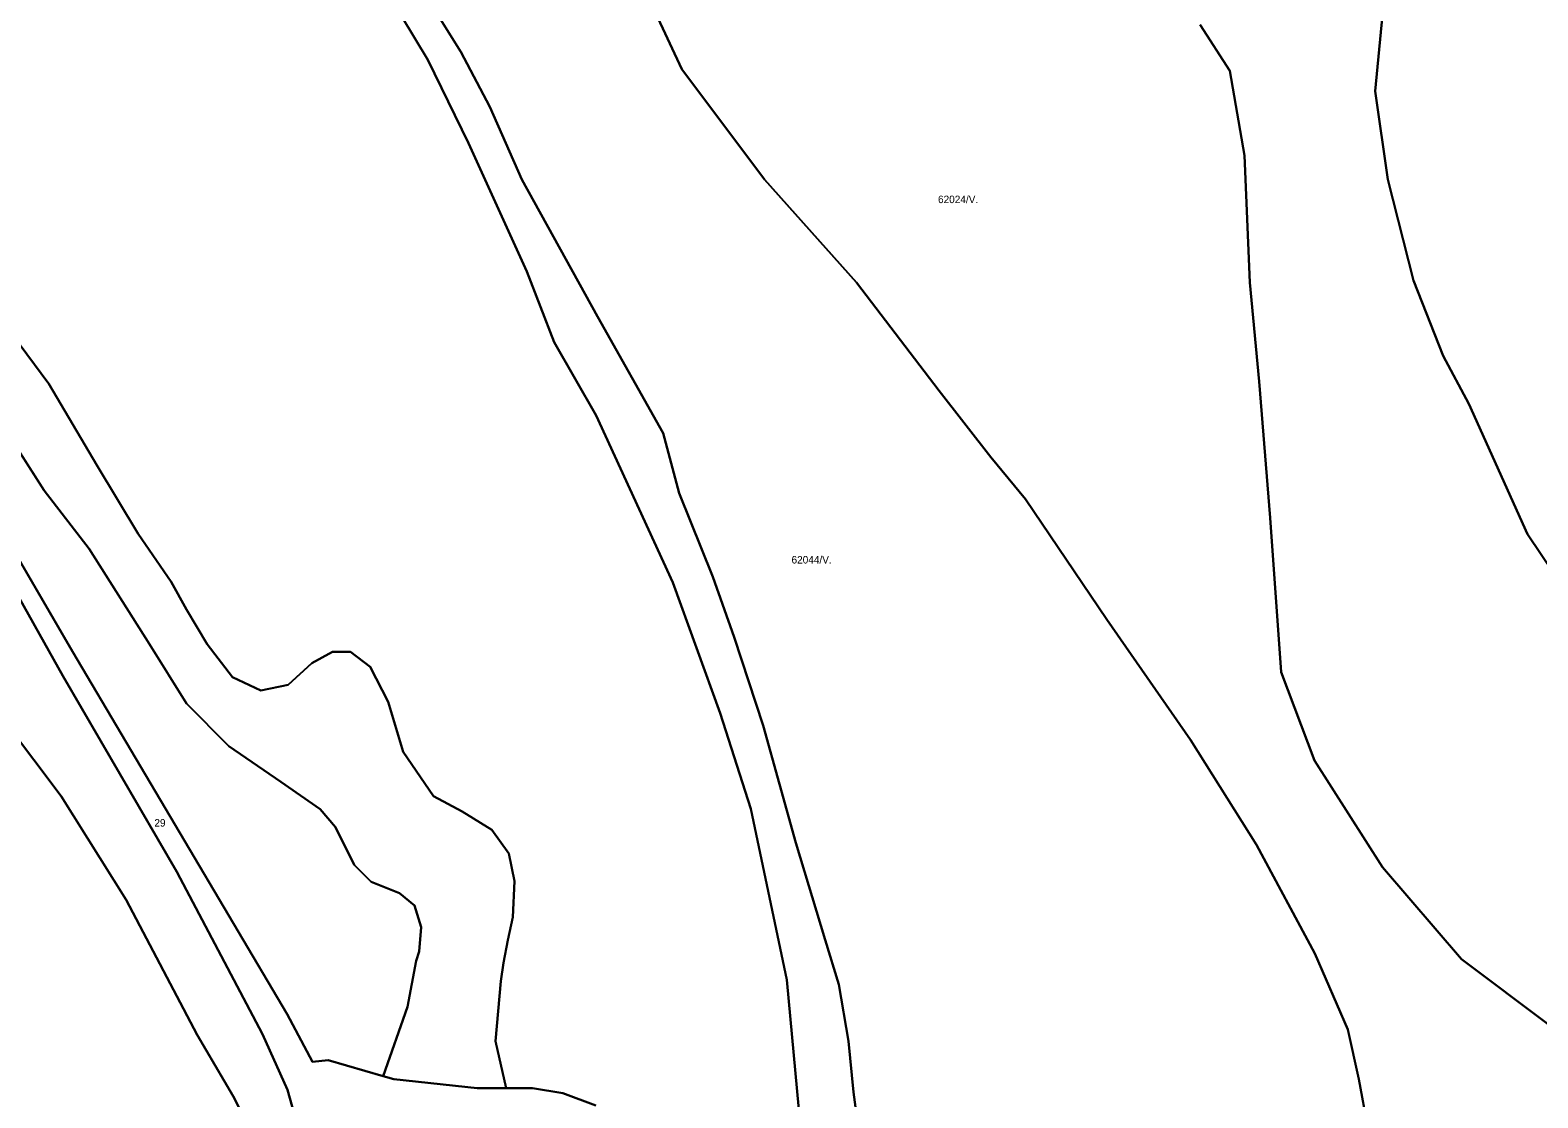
# Model space of a CAD drawing. Extents: x -521621 to -516761, y -1190184 to -1184927.
# Drawn here: x -519227 to -518423, y -1189352 to -1188783 of the extents above; entities that cross this region are included whole.
import ezdxf

# ---------------------------------------------------------------- set-up
doc = ezdxf.new("R2010")
doc.units = 0
doc.layers.add('BPEJ_s', color=7, linetype='Continuous')

msp = doc.modelspace()

# ---------------------------------------------------------------- linework, layer by layer
at = {"layer": 'BPEJ_s'}
for p, q in [((-519204.35, -1189113.86), (-519310.72, -1188931.27)), ((-519250.65, -1188979.3), (-519219.5, -1189028.08)), ((-519219.5, -1189028.08), (-519195.38, -1189059.25)), ((-519195.38, -1189059.25), (-519163.22, -1189110.04)), ((-519163.22, -1189110.04), (-519143.62, -1189141.72)), ((-519089.99, -1189307.34), (-519204.35, -1189113.86)), ((-519143.62, -1189141.72), (-519121, -1189164.34)), ((-519121, -1189164.34), (-519093.37, -1189183.45)), ((-519093.37, -1189183.45), (-519072.26, -1189198.03)), ((-519072.26, -1189198.03), (-519064.22, -1189207.59)), ((-519064.22, -1189207.59), (-519054.17, -1189227.7)), ((-519054.17, -1189227.7), (-519045.12, -1189236.75)), ((-519045.12, -1189236.75), (-519030.05, -1189242.79)), ((-519030.05, -1189242.79), (-519022.01, -1189249.32)), ((-519022.01, -1189249.32), (-519018.49, -1189260.89)), ((-519018.49, -1189260.89), (-519019.49, -1189273.96)), ((-519021.1, -1189278.81), (-519025.79, -1189303.35)), ((-519019.49, -1189273.96), (-519021.1, -1189278.81)), ((-519025.79, -1189303.35), (-519038.72, -1189340.28)), ((-519076.34, -1189332.79), (-519089.99, -1189307.34)), ((-519068.07, -1189331.87), (-519076.34, -1189332.79)), ((-519038.72, -1189340.28), (-519068.07, -1189331.87))]:
    msp.add_line(p, q, dxfattribs=at)
for points in [[(-518400.33, -1189093.59), (-518428.75, -1189051.42), (-518460.11, -1188981.79), (-518473.83, -1188956.29), (-518489.52, -1188916.08), (-518503.24, -1188862.15), (-518510.1, -1188815.07), (-518505.2, -1188765.06), (-518492.46, -1188712.1), (-518488.37, -1188692.13), (-518479.25, -1188663.96), (-518477.66, -1188644.92), (-518480.44, -1188633.02)], [(-518921.73, -1188713.08), (-518879.59, -1188803.31), (-518835.48, -1188862.15), (-518786.48, -1188917.07), (-518742.38, -1188974.93), (-518714.93, -1189010.23), (-518696.47, -1189032.67), (-518653, -1189096.87), (-518608.49, -1189161.08), (-518573.3, -1189217), (-518542.26, -1189275), (-518524.66, -1189315.39), (-518518.65, -1189341.97), (-518513.96, -1189367.96)], [(-518513.96, -1189367.96), (-518518.65, -1189341.97), (-518524.66, -1189315.39), (-518542.26, -1189275), (-518573.3, -1189217), (-518608.49, -1189161.08), (-518653, -1189096.87), (-518696.47, -1189032.67), (-518714.93, -1189010.23), (-518742.38, -1188974.93), (-518786.48, -1188917.07), (-518835.48, -1188862.15), (-518879.59, -1188803.31), (-518921.73, -1188713.08)], [(-518814.59, -1189386.96), (-518823.53, -1189288.99), (-518842.71, -1189197.76), (-518859.06, -1189146.72), (-518884.34, -1189077.07), (-518925.28, -1188988.03), (-518947.64, -1188949.04), (-518962.1, -1188911.34), (-518993.26, -1188842.89), (-519014.92, -1188798.36), (-519036.31, -1188762.86)], [(-519036.31, -1188762.86), (-519014.92, -1188798.36), (-518993.26, -1188842.89), (-518962.1, -1188911.34), (-518947.64, -1188949.04), (-518925.28, -1188988.03), (-518884.34, -1189077.07), (-518859.06, -1189146.72), (-518842.71, -1189197.76), (-518823.53, -1189288.99), (-518814.59, -1189386.96)], [(-518505.2, -1188765.06), (-518510.1, -1188815.07), (-518503.24, -1188862.15), (-518489.52, -1188916.08), (-518473.83, -1188956.29), (-518460.11, -1188981.79), (-518428.75, -1189051.42), (-518400.33, -1189093.59)], [(-519008.42, -1188776.51), (-518997.38, -1188794.11), (-518981.84, -1188823.56), (-518964.77, -1188862.16), (-518924.56, -1188935.31), (-518889.53, -1188997.54), (-518880.94, -1189029.44), (-518862.96, -1189074.01), (-518851.66, -1189106.34), (-518836.25, -1189153.42), (-518818.83, -1189215.93), (-518803.24, -1189267.62), (-518795.9, -1189291.45), (-518790.73, -1189321.78), (-518788.02, -1189348.82), (-518784.77, -1189374.22)], [(-518784.77, -1189374.22), (-518788.02, -1189348.82), (-518790.73, -1189321.78), (-518795.9, -1189291.45), (-518803.24, -1189267.62), (-518818.83, -1189215.93), (-518836.25, -1189153.42), (-518851.66, -1189106.34), (-518862.96, -1189074.01), (-518880.94, -1189029.44), (-518889.53, -1188997.54), (-518924.56, -1188935.31), (-518964.77, -1188862.16), (-518981.84, -1188823.56), (-518997.38, -1188794.11), (-519008.42, -1188776.51)], [(-518416.99, -1189313.26), (-518464.04, -1189277.96), (-518506.18, -1189228.92), (-518542.44, -1189172.04), (-518560.08, -1189124.97), (-518565.96, -1189042.59), (-518571.84, -1188970.02), (-518576.74, -1188917.07), (-518579.68, -1188849.4), (-518587.52, -1188804.29), (-518603.21, -1188779.77)], [(-518603.21, -1188779.77), (-518587.52, -1188804.29), (-518579.68, -1188849.4), (-518576.74, -1188917.07), (-518571.84, -1188970.02), (-518565.96, -1189042.59), (-518560.08, -1189124.97), (-518542.44, -1189172.04), (-518506.18, -1189228.92), (-518464.04, -1189277.96), (-518416.99, -1189313.26)], [(-519310.72, -1188931.27), (-519204.35, -1189113.86), (-519089.99, -1189307.34), (-519076.34, -1189332.79), (-519068.07, -1189331.87), (-519038.72, -1189340.28), (-519033.11, -1189341.89), (-518988.67, -1189346.71), (-518973.16, -1189346.77), (-518959.12, -1189346.82), (-518943.04, -1189349.41), (-518925.38, -1189356.01)], [(-519244.62, -1188934.05), (-519216.99, -1188971.26), (-519191.36, -1189014.5), (-519169.25, -1189051.21), (-519151.66, -1189076.85), (-519143.62, -1189091.43), (-519132.56, -1189110.04), (-519118.99, -1189127.64), (-519103.92, -1189134.68), (-519089.35, -1189131.66), (-519076.78, -1189120.09), (-519065.73, -1189114.06), (-519056.18, -1189114.06), (-519045.63, -1189122.1), (-519036.08, -1189140.71), (-519028.04, -1189167.36), (-519011.96, -1189190.99), (-518996.65, -1189199.29), (-518980.88, -1189209.04), (-518971.71, -1189221.66), (-518968.84, -1189236.29), (-518969.7, -1189255.51), (-518972.28, -1189267.84), (-518974.57, -1189279.89), (-518976.01, -1189289.64), (-518978.9, -1189321.76), (-518973.16, -1189346.77), (-518988.67, -1189346.71), (-519033.11, -1189341.89), (-519038.72, -1189340.28), (-519025.79, -1189303.35), (-519021.1, -1189278.81), (-519019.49, -1189273.96), (-519018.49, -1189260.89), (-519022.01, -1189249.32), (-519030.05, -1189242.79), (-519045.12, -1189236.75), (-519054.17, -1189227.7), (-519064.22, -1189207.59), (-519072.26, -1189198.03), (-519093.37, -1189183.45), (-519121, -1189164.34), (-519143.62, -1189141.72), (-519163.22, -1189110.04), (-519195.38, -1189059.25), (-519219.5, -1189028.08), (-519250.65, -1188979.3)], [(-518925.38, -1189356.01), (-518943.04, -1189349.41), (-518959.12, -1189346.82), (-518973.16, -1189346.77), (-518978.9, -1189321.76), (-518976.01, -1189289.64), (-518974.57, -1189279.89), (-518972.28, -1189267.84), (-518969.7, -1189255.51), (-518968.84, -1189236.29), (-518971.71, -1189221.66), (-518980.88, -1189209.04), (-518996.65, -1189199.29), (-519011.96, -1189190.99), (-519028.04, -1189167.36), (-519036.08, -1189140.71), (-519045.63, -1189122.1), (-519056.18, -1189114.06), (-519065.73, -1189114.06), (-519076.78, -1189120.09), (-519089.35, -1189131.66), (-519103.92, -1189134.68), (-519118.99, -1189127.64), (-519132.56, -1189110.04), (-519143.62, -1189091.43), (-519151.66, -1189076.85), (-519169.25, -1189051.21), (-519191.36, -1189014.5), (-519216.99, -1188971.26), (-519244.62, -1188934.05)], [(-519271.12, -1189017.05), (-519209.47, -1189126.94), (-519148.66, -1189231.39), (-519103.08, -1189317.95), (-519089.69, -1189347.71), (-519083.59, -1189369.88)], [(-519083.59, -1189369.88), (-519089.69, -1189347.71), (-519103.08, -1189317.95), (-519148.66, -1189231.39), (-519209.47, -1189126.94), (-519271.12, -1189017.05)], [(-519094.83, -1189397.35), (-519118.62, -1189351.02), (-519137.83, -1189318.32), (-519175.78, -1189246.31), (-519210.45, -1189190.99), (-519239.6, -1189152.28)], [(-519239.6, -1189152.28), (-519210.45, -1189190.99), (-519175.78, -1189246.31), (-519137.83, -1189318.32), (-519118.62, -1189351.02), (-519094.83, -1189397.35)]]:
    msp.add_lwpolyline(points, dxfattribs=at)

# ---------------------------------------------------------------- texts
for s, p in [('62024/V.', (-518743.02, -1188874.82)), ('62044/V.', (-518821.1, -1189067)), ('29', (-519160.69, -1189207.28))]:
    msp.add_text(s, height=4, dxfattribs=at).set_placement(p)

doc.saveas('drawing.dxf')
